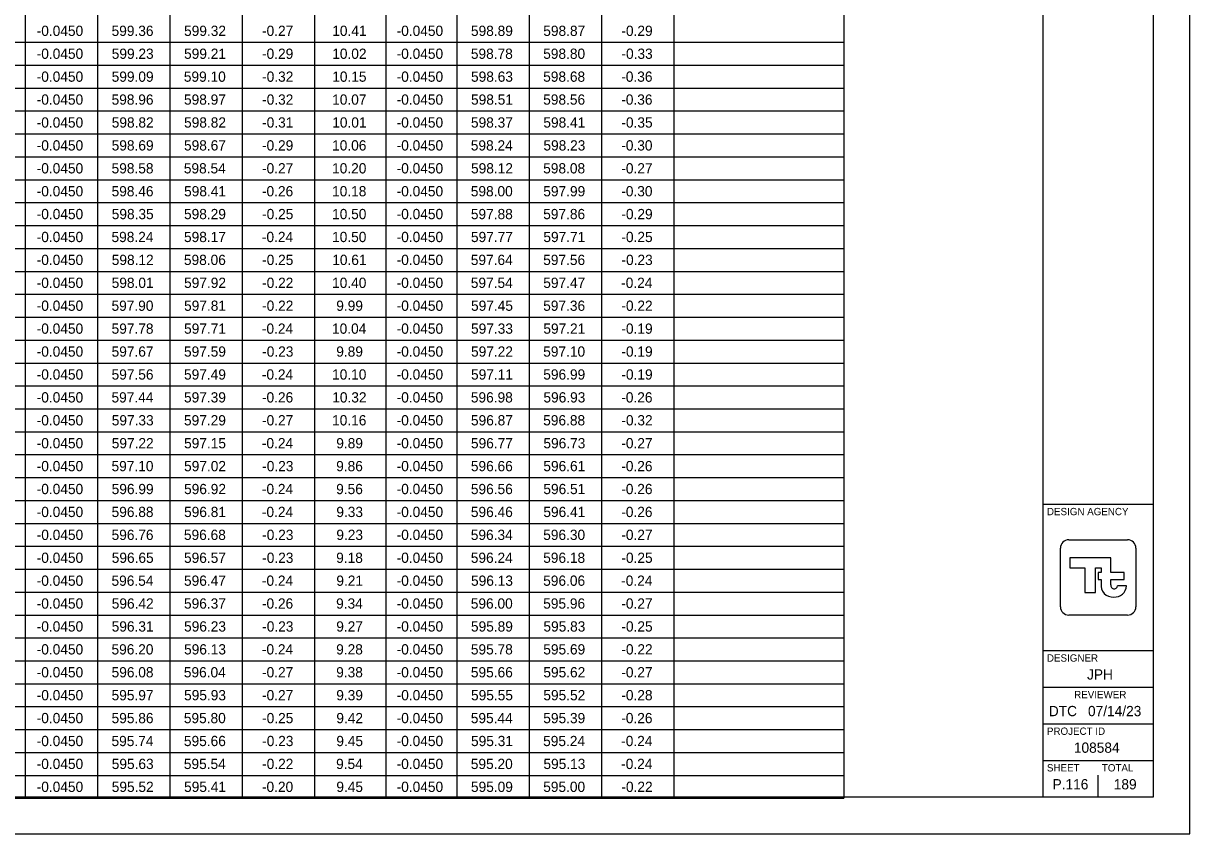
# Model space of a CAD drawing. Extents: x 0 to 34, y 0 to 22.
# Drawn here: x 18.07 to 34, y 0 to 11.07 of the extents above; entities that cross this region are included whole.
import ezdxf

# ---------------------------------------------------------------- set-up
doc = ezdxf.new("R2010")
doc.units = 0
for name, color, linetype in [('SH_Border', 7, 'Continuous'), ('SH_Cut_Line', 7, 'Continuous'), ('SH_Data', 7, 'Continuous'), ('SH_Text', 7, 'Continuous')]:
    doc.layers.add(name, color=color, linetype=linetype)

msp = doc.modelspace()

# ---------------------------------------------------------------- linework, layer by layer
at = {"layer": 'SH_Border'}
for p, q in [((32, 0.5), (32, 21.5)), ((32, 4.5), (33.5, 4.5)), ((32, 2.5), (33.5, 2.5)), ((32, 2), (33.5, 2)), ((32, 1.5), (33.5, 1.5)), ((32, 1), (33.5, 1))]:
    msp.add_line(p, q, dxfattribs=at)
msp.add_lwpolyline([(1.5, 21.5), (33.5, 21.5), (33.5, 0.5), (1.5, 0.5)], close=True, dxfattribs=at)
at = {"layer": 'SH_Cut_Line'}
msp.add_lwpolyline([(0, 0), (34, 0), (34, 22), (0, 22)], close=True, dxfattribs=at)
at = {"layer": 'SH_Data'}
for p, q in [((32.75, 3.5), (32.75, 3.5)), ((32.791, 3.415), (32.791, 3.415)), ((33.136, 3.385), (33.015, 3.385)), ((32.75, 0.5), (32.75, 0.8)), ((32.375, 0.675), (32.375, 0.675))]:
    msp.add_line(p, q, dxfattribs=at)
for points in [[(32.348, 4.014), (33.152, 4.014)], [(32.236, 3.099), (32.236, 3.901)], [(33.264, 3.901), (33.264, 3.099)], [(32.922, 3.399), (32.922, 3.47), (33.107, 3.47), (33.107, 3.568), (32.922, 3.568), (32.922, 3.768), (32.361, 3.768), (32.361, 3.632), (32.566, 3.632), (32.566, 3.294), (32.715, 3.294), (32.715, 3.63), (32.79, 3.63), (32.79, 3.568), (32.748, 3.568), (32.748, 3.47), (32.79, 3.47), (32.79, 3.415), (32.791, 3.415)], [(33.152, 2.986), (32.348, 2.986)]]:
    msp.add_lwpolyline(points, dxfattribs=at)
for centre, radius, start, end in [((32.348, 3.901), 0.113, 90, 180), ((33.152, 3.901), 0.113, 360, 90), ((32.949, 3.392), 0.16, 171.8856, 274.8323), ((32.968, 3.392), 0.0473, 171.8856, 350.9243), ((32.976, 3.392), 0.16, 265.1677, 357.3201), ((32.348, 3.099), 0.113, 180, 270), ((33.152, 3.099), 0.113, 270, 360)]:
    msp.add_arc(centre, radius, start, end, dxfattribs=at)
at = {"layer": 'SH_Text'}
for p, q in [((29.277, 21.5), (29.277, 0.484)), ((26.954, 20.396), (26.954, 0.484)), ((22.046, 19.853), (22.046, 0.484)), ((18.093, 19.54), (18.093, 0.484)), ((19.081, 19.54), (19.081, 0.484)), ((20.07, 19.54), (20.07, 0.484)), ((21.058, 19.54), (21.058, 0.484)), ((23.018, 19.54), (23.018, 0.484)), ((23.99, 19.54), (23.99, 0.484)), ((24.978, 19.54), (24.978, 0.484)), ((25.966, 19.54), (25.966, 0.484)), ((4.225, 10.811), (29.277, 10.811)), ((4.225, 10.498), (29.277, 10.498)), ((4.225, 10.185), (29.277, 10.185)), ((4.225, 9.872), (29.277, 9.872)), ((4.225, 9.559), (29.277, 9.559)), ((4.225, 9.246), (29.277, 9.246)), ((4.225, 8.933), (29.277, 8.933)), ((4.225, 8.62), (29.277, 8.62)), ((4.225, 8.307), (29.277, 8.307)), ((4.225, 7.994), (29.277, 7.994)), ((4.225, 7.681), (29.277, 7.681)), ((4.225, 7.368), (29.277, 7.368)), ((4.225, 7.055), (29.277, 7.055)), ((4.225, 6.742), (29.277, 6.742)), ((4.225, 6.429), (29.277, 6.429)), ((4.225, 6.116), (29.277, 6.116)), ((4.225, 5.804), (29.277, 5.804)), ((4.225, 5.491), (29.277, 5.491)), ((4.225, 5.178), (29.277, 5.178)), ((4.225, 4.865), (29.277, 4.865)), ((4.225, 4.552), (29.277, 4.552)), ((4.225, 4.239), (29.277, 4.239)), ((4.225, 3.926), (29.277, 3.926)), ((4.225, 3.613), (29.277, 3.613)), ((4.225, 3.3), (29.277, 3.3)), ((4.225, 2.987), (29.277, 2.987)), ((4.225, 2.674), (29.277, 2.674)), ((4.225, 2.361), (29.277, 2.361)), ((4.225, 2.048), (29.277, 2.048)), ((4.225, 1.735), (29.277, 1.735)), ((4.225, 1.422), (29.277, 1.422)), ((4.225, 1.109), (29.277, 1.109)), ((4.225, 0.796), (29.277, 0.796)), ((4.225, 0.484), (29.277, 0.484))]:
    msp.add_line(p, q, dxfattribs=at)

# ---------------------------------------------------------------- texts
at = {"layer": 'SH_Data'}
for s, height, p in [('DESIGN AGENCY', 0.1, (32.05, 4.35)), ('DESIGNER', 0.1, (32.05, 2.35)), ('JPH', 0.14, (32.598, 2.105)), ('REVIEWER', 0.1, (32.422, 1.85)), ('DTC', 0.14, (32.076, 1.605)), ('07/14/23', 0.14, (32.611, 1.605)), ('PROJECT ID', 0.1, (32.05, 1.35)), ('108584', 0.14, (32.418, 1.105)), ('SHEET', 0.1, (32.05, 0.85)), ('TOTAL', 0.1, (32.8, 0.85)), ('P.116', 0.14, (32.127, 0.605)), ('189', 0.14, (32.963, 0.605))]:
    msp.add_text(s, height=height, dxfattribs=at).set_placement(p)
at = {"layer": 'SH_Text'}
for s, p in [('-0.0450', (18.25, 10.897)), ('599.36', (19.273, 10.897)), ('599.32', (20.263, 10.897)), ('-0.27', (21.328, 10.897)), ('10.41', (22.287, 10.897)), ('-0.0450', (23.167, 10.897)), ('598.89', (24.182, 10.897)), ('598.87', (25.17, 10.897)), ('-0.29', (26.237, 10.897)), ('-0.0450', (18.25, 10.584)), ('599.23', (19.275, 10.584)), ('599.21', (20.263, 10.584)), ('-0.29', (21.328, 10.584)), ('10.02', (22.287, 10.584)), ('-0.0450', (23.167, 10.584)), ('598.78', (24.181, 10.584)), ('598.80', (25.169, 10.584)), ('-0.33', (26.238, 10.584)), ('-0.0450', (18.25, 10.271)), ('599.09', (19.274, 10.271)), ('599.10', (20.26, 10.271)), ('-0.32', (21.329, 10.271)), ('10.15', (22.287, 10.271)), ('-0.0450', (23.167, 10.271)), ('598.63', (24.183, 10.271)), ('598.68', (25.169, 10.271)), ('-0.36', (26.235, 10.271)), ('-0.0450', (18.25, 9.958)), ('598.96', (19.273, 9.958)), ('598.97', (20.262, 9.958)), ('-0.32', (21.329, 9.958)), ('10.07', (22.286, 9.958)), ('-0.0450', (23.167, 9.958)), ('598.51', (24.183, 9.958)), ('598.56', (25.169, 9.958)), ('-0.36', (26.235, 9.958)), ('-0.0450', (18.25, 9.645)), ('598.82', (19.275, 9.645)), ('598.82', (20.263, 9.645)), ('-0.31', (21.329, 9.645)), ('10.01', (22.287, 9.645)), ('-0.0450', (23.167, 9.645)), ('598.37', (24.182, 9.645)), ('598.41', (25.171, 9.645)), ('-0.35', (26.237, 9.645)), ('-0.0450', (18.25, 9.332)), ('598.69', (19.274, 9.332)), ('598.67', (20.262, 9.332)), ('-0.29', (21.328, 9.332)), ('10.06', (22.285, 9.332)), ('-0.0450', (23.167, 9.332)), ('598.24', (24.18, 9.332)), ('598.23', (25.172, 9.332)), ('-0.30', (26.235, 9.332)), ('-0.0450', (18.25, 9.019)), ('598.58', (19.273, 9.019)), ('598.54', (20.26, 9.019)), ('-0.27', (21.328, 9.019)), ('10.20', (22.285, 9.019)), ('-0.0450', (23.167, 9.019)), ('598.12', (24.183, 9.019)), ('598.08', (25.169, 9.019)), ('-0.27', (26.236, 9.019)), ('-0.0450', (18.25, 8.706)), ('598.46', (19.273, 8.706)), ('598.41', (20.263, 8.706)), ('-0.26', (21.327, 8.706)), ('10.18', (22.285, 8.706)), ('-0.0450', (23.167, 8.706)), ('598.00', (24.18, 8.706)), ('597.99', (25.17, 8.706)), ('-0.30', (26.235, 8.706)), ('-0.0450', (18.25, 8.394)), ('598.35', (19.275, 8.394)), ('598.29', (20.262, 8.394)), ('-0.25', (21.329, 8.394)), ('10.50', (22.285, 8.394)), ('-0.0450', (23.167, 8.394)), ('597.88', (24.181, 8.394)), ('597.86', (25.169, 8.394)), ('-0.29', (26.237, 8.394)), ('-0.0450', (18.25, 8.081)), ('598.24', (19.272, 8.081)), ('598.17', (20.262, 8.081)), ('-0.24', (21.326, 8.081)), ('10.50', (22.285, 8.081)), ('-0.0450', (23.167, 8.081)), ('597.77', (24.182, 8.081)), ('597.71', (25.171, 8.081)), ('-0.25', (26.237, 8.081)), ('-0.0450', (18.25, 7.768)), ('598.12', (19.275, 7.768)), ('598.06', (20.261, 7.768)), ('-0.25', (21.329, 7.768)), ('10.61', (22.287, 7.768)), ('-0.0450', (23.167, 7.768)), ('597.64', (24.18, 7.768)), ('597.56', (25.169, 7.768)), ('-0.23', (26.238, 7.768)), ('-0.0450', (18.25, 7.455)), ('598.01', (19.274, 7.455)), ('597.92', (20.263, 7.455)), ('-0.22', (21.329, 7.455)), ('10.40', (22.285, 7.455)), ('-0.0450', (23.167, 7.455)), ('597.54', (24.18, 7.455)), ('597.47', (25.17, 7.455)), ('-0.24', (26.234, 7.455)), ('-0.0450', (18.25, 7.142)), ('597.90', (19.272, 7.142)), ('597.81', (20.263, 7.142)), ('-0.22', (21.329, 7.142)), ('9.99', (22.342, 7.142)), ('-0.0450', (23.167, 7.142)), ('597.45', (24.183, 7.142)), ('597.36', (25.169, 7.142)), ('-0.22', (26.237, 7.142)), ('-0.0450', (18.25, 6.829)), ('597.78', (19.273, 6.829)), ('597.71', (20.263, 6.829)), ('-0.24', (21.326, 6.829)), ('10.04', (22.284, 6.829)), ('-0.0450', (23.167, 6.829)), ('597.33', (24.183, 6.829)), ('597.21', (25.171, 6.829)), ('-0.19', (26.237, 6.829)), ('-0.0450', (18.25, 6.516)), ('597.67', (19.273, 6.516)), ('597.59', (20.262, 6.516)), ('-0.23', (21.33, 6.516)), ('9.89', (22.342, 6.516)), ('-0.0450', (23.167, 6.516)), ('597.22', (24.183, 6.516)), ('597.10', (25.169, 6.516)), ('-0.19', (26.237, 6.516)), ('-0.0450', (18.25, 6.203)), ('597.56', (19.273, 6.203)), ('597.49', (20.262, 6.203)), ('-0.24', (21.326, 6.203)), ('10.10', (22.285, 6.203)), ('-0.0450', (23.167, 6.203)), ('597.11', (24.183, 6.203)), ('596.99', (25.17, 6.203)), ('-0.19', (26.237, 6.203)), ('-0.0450', (18.25, 5.89)), ('597.44', (19.272, 5.89)), ('597.39', (20.262, 5.89)), ('-0.26', (21.327, 5.89)), ('10.32', (22.287, 5.89)), ('-0.0450', (23.167, 5.89)), ('596.98', (24.181, 5.89)), ('596.93', (25.172, 5.89)), ('-0.26', (26.235, 5.89)), ('-0.0450', (18.25, 5.577)), ('597.33', (19.275, 5.577)), ('597.29', (20.262, 5.577)), ('-0.27', (21.328, 5.577)), ('10.16', (22.285, 5.577)), ('-0.0450', (23.167, 5.577)), ('596.87', (24.182, 5.577)), ('596.88', (25.169, 5.577)), ('-0.32', (26.237, 5.577)), ('-0.0450', (18.25, 5.264)), ('597.22', (19.275, 5.264)), ('597.15', (20.263, 5.264)), ('-0.24', (21.326, 5.264)), ('9.89', (22.342, 5.264)), ('-0.0450', (23.167, 5.264)), ('596.77', (24.182, 5.264)), ('596.73', (25.172, 5.264)), ('-0.27', (26.236, 5.264)), ('-0.0450', (18.25, 4.951)), ('597.10', (19.272, 4.951)), ('597.02', (20.263, 4.951)), ('-0.23', (21.33, 4.951)), ('9.86', (22.341, 4.951)), ('-0.0450', (23.167, 4.951)), ('596.66', (24.181, 4.951)), ('596.61', (25.171, 4.951)), ('-0.26', (26.235, 4.951)), ('-0.0450', (18.25, 4.638)), ('596.99', (19.274, 4.638)), ('596.92', (20.263, 4.638)), ('-0.24', (21.326, 4.638)), ('9.56', (22.341, 4.638)), ('-0.0450', (23.167, 4.638)), ('596.56', (24.181, 4.638)), ('596.51', (25.171, 4.638)), ('-0.26', (26.235, 4.638)), ('-0.0450', (18.25, 4.325)), ('596.88', (19.273, 4.325)), ('596.81', (20.263, 4.325)), ('-0.24', (21.326, 4.325)), ('9.33', (22.343, 4.325)), ('-0.0450', (23.167, 4.325)), ('596.46', (24.181, 4.325)), ('596.41', (25.171, 4.325)), ('-0.26', (26.235, 4.325)), ('-0.0450', (18.25, 4.012)), ('596.76', (19.273, 4.012)), ('596.68', (20.261, 4.012)), ('-0.23', (21.33, 4.012)), ('9.23', (22.343, 4.012)), ('-0.0450', (23.167, 4.012)), ('596.34', (24.18, 4.012)), ('596.30', (25.169, 4.012)), ('-0.27', (26.236, 4.012)), ('-0.0450', (18.25, 3.699)), ('596.65', (19.275, 3.699)), ('596.57', (20.262, 3.699)), ('-0.23', (21.33, 3.699)), ('9.18', (22.341, 3.699)), ('-0.0450', (23.167, 3.699)), ('596.24', (24.18, 3.699)), ('596.18', (25.169, 3.699)), ('-0.25', (26.237, 3.699)), ('-0.0450', (18.25, 3.386)), ('596.54', (19.272, 3.386)), ('596.47', (20.262, 3.386)), ('-0.24', (21.326, 3.386)), ('9.21', (22.343, 3.386)), ('-0.0450', (23.167, 3.386)), ('596.13', (24.183, 3.386)), ('596.06', (25.169, 3.386)), ('-0.24', (26.234, 3.386)), ('-0.0450', (18.25, 3.074)), ('596.42', (19.275, 3.074)), ('596.37', (20.262, 3.074)), ('-0.26', (21.327, 3.074)), ('9.34', (22.34, 3.074)), ('-0.0450', (23.167, 3.074)), ('596.00', (24.18, 3.074)), ('595.96', (25.169, 3.074)), ('-0.27', (26.236, 3.074)), ('-0.0450', (18.25, 2.761)), ('596.31', (19.274, 2.761)), ('596.23', (20.263, 2.761)), ('-0.23', (21.33, 2.761)), ('9.27', (22.342, 2.761)), ('-0.0450', (23.167, 2.761)), ('595.89', (24.182, 2.761)), ('595.83', (25.172, 2.761)), ('-0.25', (26.237, 2.761)), ('-0.0450', (18.25, 2.448)), ('596.20', (19.272, 2.448)), ('596.13', (20.263, 2.448)), ('-0.24', (21.326, 2.448)), ('9.28', (22.341, 2.448)), ('-0.0450', (23.167, 2.448)), ('595.78', (24.181, 2.448)), ('595.69', (25.17, 2.448)), ('-0.22', (26.237, 2.448)), ('-0.0450', (18.25, 2.135)), ('596.08', (19.273, 2.135)), ('596.04', (20.26, 2.135)), ('-0.27', (21.328, 2.135)), ('9.38', (22.341, 2.135)), ('-0.0450', (23.167, 2.135)), ('595.66', (24.181, 2.135)), ('595.62', (25.171, 2.135)), ('-0.27', (26.236, 2.135)), ('-0.0450', (18.25, 1.822)), ('595.97', (19.273, 1.822)), ('595.93', (20.263, 1.822)), ('-0.27', (21.328, 1.822)), ('9.39', (22.342, 1.822)), ('-0.0450', (23.167, 1.822)), ('595.55', (24.183, 1.822)), ('595.52', (25.171, 1.822)), ('-0.28', (26.236, 1.822)), ('-0.0450', (18.25, 1.509)), ('595.86', (19.273, 1.509)), ('595.80', (20.26, 1.509)), ('-0.25', (21.329, 1.509)), ('9.42', (22.343, 1.509)), ('-0.0450', (23.167, 1.509)), ('595.44', (24.18, 1.509)), ('595.39', (25.17, 1.509)), ('-0.26', (26.235, 1.509)), ('-0.0450', (18.25, 1.196)), ('595.74', (19.272, 1.196)), ('595.66', (20.261, 1.196)), ('-0.23', (21.33, 1.196)), ('9.45', (22.343, 1.196)), ('-0.0450', (23.167, 1.196)), ('595.31', (24.183, 1.196)), ('595.24', (25.168, 1.196)), ('-0.24', (26.234, 1.196)), ('-0.0450', (18.25, 0.883)), ('595.63', (19.275, 0.883)), ('595.54', (20.26, 0.883)), ('-0.22', (21.329, 0.883)), ('9.54', (22.34, 0.883)), ('-0.0450', (23.167, 0.883)), ('595.20', (24.18, 0.883)), ('595.13', (25.172, 0.883)), ('-0.24', (26.234, 0.883)), ('-0.0450', (18.25, 0.57)), ('595.52', (19.275, 0.57)), ('595.41', (20.263, 0.57)), ('-0.20', (21.327, 0.57)), ('9.45', (22.343, 0.57)), ('-0.0450', (23.167, 0.57)), ('595.09', (24.182, 0.57)), ('595.00', (25.169, 0.57)), ('-0.22', (26.237, 0.57))]:
    msp.add_text(s, height=0.14, dxfattribs=at).set_placement(p)

doc.saveas('drawing.dxf')
